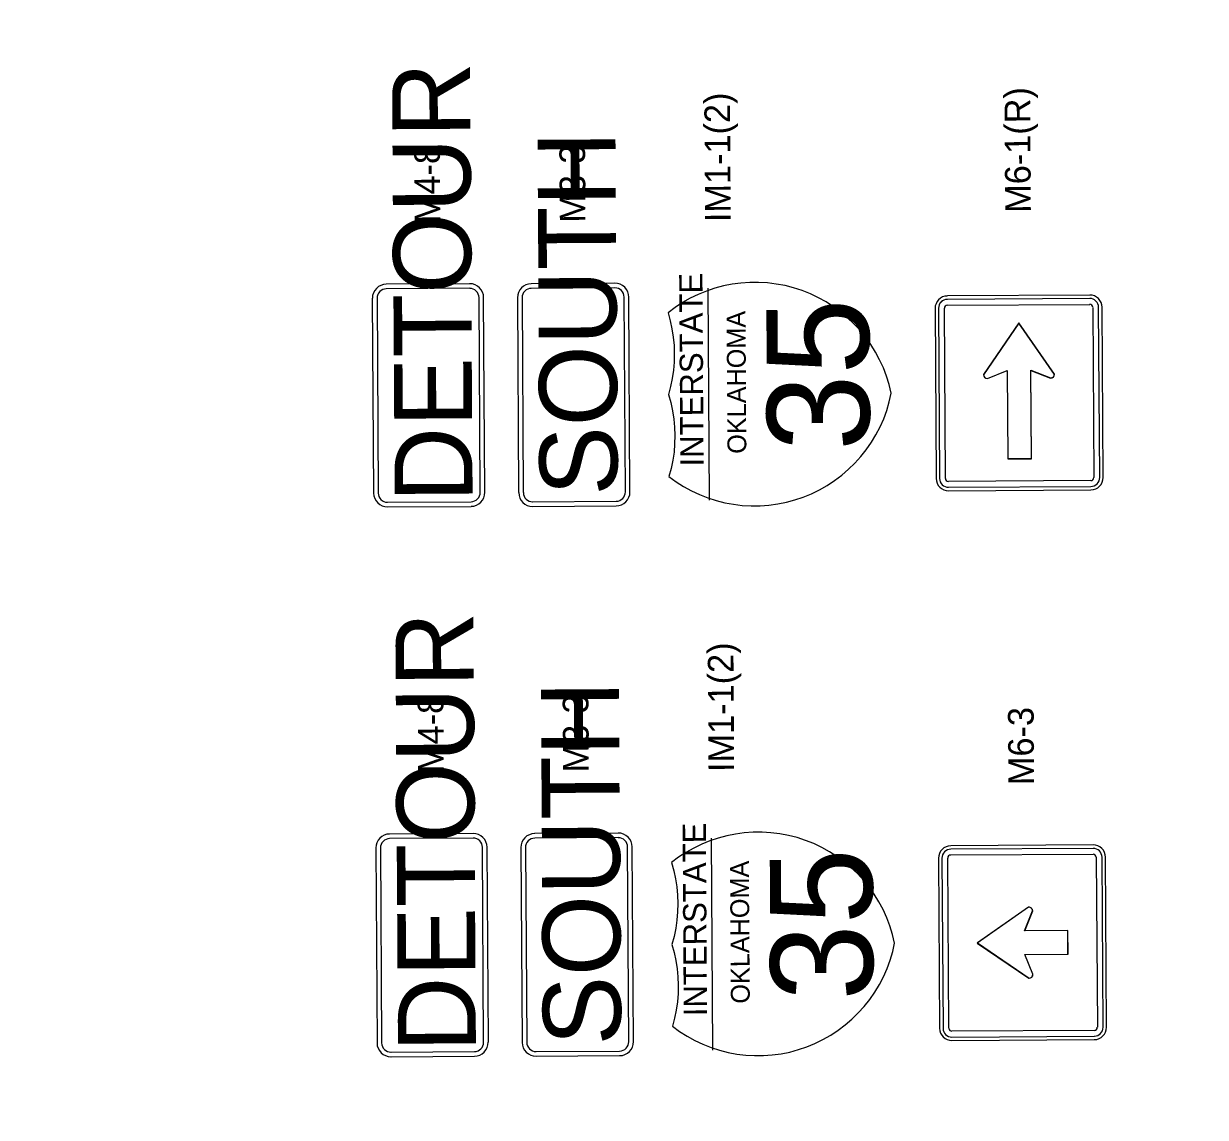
# Model space of a CAD drawing. Extents: x 2135767 to 2151731, y 141839 to 175894.
# Drawn here: x 2139084 to 2140190, y 172875 to 173899 of the extents above; entities that cross this region are included whole.
import ezdxf

# ---------------------------------------------------------------- set-up
doc = ezdxf.new("R2010")
doc.units = 0
doc.layers.add('PR_Phasing_Detour_1', color=7, linetype='Continuous')

msp = doc.modelspace()

# ---------------------------------------------------------------- linework, layer by layer
at = {"layer": 'PR_Phasing_Detour_1'}
for p, q in [((2139501.8, 173655.2), (2139423.7, 173654.7)), ((2139637.6, 173655.7), (2139559.5, 173655.2)), ((2139501.9, 173650.9), (2139423.7, 173650.4)), ((2139511.7, 173459.9), (2139510.6, 173642.2)), ((2139516.1, 173459.9), (2139514.9, 173642.3)), ((2139546.5, 173642.1), (2139547.6, 173459.7)), ((2139550.9, 173642.1), (2139552, 173459.8)), ((2139637.6, 173651.3), (2139559.5, 173650.8)), ((2139647.5, 173460.4), (2139646.4, 173642.7)), ((2139651.8, 173460.4), (2139650.7, 173642.7)), ((2139726.1, 173452.5), (2139724.9, 173650.9)), ((2140082, 173644.6), (2139948.8, 173643.8)), ((2139410.7, 173641.6), (2139411.9, 173459.3)), ((2139415.1, 173641.7), (2139416.2, 173459.3)), ((2139937.3, 173632.2), (2139938.3, 173472.9)), ((2139940.5, 173632.2), (2139941.5, 173472.9)), ((2139940.5, 173632.2), (2139941.5, 173473)), ((2139947, 173473), (2139946, 173632.2)), ((2139947, 173473), (2139946, 173632.2)), ((2140082, 173641.4), (2139948.8, 173640.5)), ((2140082, 173641.4), (2139948.8, 173640.5)), ((2139948.8, 173635.1), (2140082, 173635.9)), ((2139948.8, 173635.1), (2140082, 173635.9)), ((2140084.9, 173633.1), (2140085.9, 173473.8)), ((2140084.9, 173633.1), (2140085.9, 173473.8)), ((2140091.3, 173473.9), (2140090.3, 173633.1)), ((2140091.3, 173473.9), (2140090.3, 173633.1)), ((2140094.6, 173473.9), (2140093.6, 173633.1)), ((2140015.5, 173618.3), (2139982.5, 173570)), ((2140049.1, 173570.4), (2140015.5, 173618.3)), ((2139986.2, 173566.4), (2140004.7, 173573.9)), ((2140004.7, 173573.9), (2140005.2, 173491.3)), ((2140027.4, 173491.4), (2140026.9, 173574)), ((2140026.9, 173574), (2140045.4, 173566.7)), ((2140005.2, 173491.3), (2140027.4, 173491.4)), ((2140083, 173471), (2139949.8, 173470.1)), ((2140083, 173471), (2139949.8, 173470.1)), ((2139949.9, 173464.7), (2140083.1, 173465.5)), ((2139949.9, 173464.7), (2140083.1, 173465.5)), ((2139949.9, 173461.5), (2140083.1, 173462.3)), ((2139425, 173450.7), (2139503.1, 173451.2)), ((2139425, 173446.3), (2139503.1, 173446.8)), ((2139560.7, 173451.1), (2139638.9, 173451.6)), ((2139560.8, 173446.8), (2139638.9, 173447.3)), ((2139505, 173140.7), (2139426.9, 173140.2)), ((2139505.1, 173136.4), (2139426.9, 173135.9)), ((2139640.8, 173141.1), (2139562.7, 173140.7)), ((2139640.8, 173136.8), (2139562.7, 173136.3)), ((2139729.3, 172938), (2139728.1, 173136.3)), ((2139413.9, 173127.1), (2139415.1, 172944.8)), ((2139418.3, 173127.1), (2139419.4, 172944.8)), ((2139514.9, 172945.4), (2139513.8, 173127.7)), ((2139519.3, 172945.4), (2139518.1, 173127.7)), ((2139549.7, 173127.6), (2139550.8, 172945.2)), ((2139554, 173127.6), (2139555.2, 172945.2)), ((2139650.7, 172945.8), (2139649.6, 173128.2)), ((2139655, 172945.9), (2139653.9, 173128.2)), ((2140085.1, 173130.1), (2139951.9, 173129.3)), ((2140085.2, 173126.8), (2139952, 173126)), ((2140085.2, 173126.8), (2139952, 173126)), ((2139940.5, 173117.7), (2139941.5, 172958.4)), ((2139943.7, 173117.7), (2139944.7, 172958.4)), ((2139943.7, 173117.7), (2139944.7, 172958.4)), ((2139950.1, 172958.5), (2139949.2, 173117.7)), ((2139950.1, 172958.5), (2139949.2, 173117.7)), ((2139952, 173120.6), (2140085.2, 173121.4)), ((2139952, 173120.6), (2140085.2, 173121.4)), ((2140088.1, 173118.6), (2140089.1, 172959.3)), ((2140088.1, 173118.6), (2140089.1, 172959.3)), ((2140094.5, 172959.4), (2140093.5, 173118.6)), ((2140094.5, 172959.4), (2140093.5, 173118.6)), ((2140097.7, 172959.4), (2140096.8, 173118.6)), ((2140024.7, 173071.8), (2139976.8, 173038.2)), ((2140021.1, 173049.6), (2140028.4, 173068.2)), ((2140061.4, 173049.9), (2140021.1, 173049.6)), ((2140061.5, 173027.7), (2140061.4, 173049.9)), ((2139976.8, 173038.2), (2140025.1, 173005.2)), ((2140021.3, 173027.4), (2140061.5, 173027.7)), ((2140028.8, 173009), (2140021.3, 173027.4)), ((2140086.2, 172956.4), (2139953, 172955.6)), ((2140086.2, 172956.4), (2139953, 172955.6)), ((2139953.1, 172950.2), (2140086.3, 172951)), ((2139953.1, 172950.2), (2140086.3, 172951)), ((2139953.1, 172946.9), (2140086.3, 172947.8)), ((2139428.2, 172936.2), (2139506.3, 172936.7)), ((2139563.9, 172936.6), (2139642.1, 172937.1)), ((2139428.2, 172931.8), (2139506.3, 172932.3)), ((2139563.9, 172932.3), (2139642.1, 172932.8))]:
    msp.add_line(p, q, dxfattribs=at)
for points in [[(2139688.3, 173474.8), (2139695, 173469.9), (2139702, 173465.5), (2139709.3, 173461.5), (2139716.8, 173458), (2139724.5, 173454.9), (2139732.5, 173452.4), (2139740.5, 173450.3), (2139748.7, 173448.8), (2139756.9, 173447.8), (2139765.2, 173447.4), (2139773.5, 173447.4), (2139781.8, 173448), (2139790, 173449.1), (2139798.2, 173450.8), (2139806.2, 173452.9), (2139814, 173455.6), (2139821.7, 173458.7), (2139829.2, 173462.4), (2139836.4, 173466.5), (2139843.3, 173471.1), (2139850, 173476.1), (2139856.3, 173481.5), (2139862.2, 173487.3), (2139867.8, 173493.4), (2139872.9, 173499.9), (2139877.7, 173506.8), (2139882, 173513.9), (2139885.8, 173521.2), (2139889.2, 173528.8), (2139892, 173536.6), (2139894.4, 173544.6), (2139896.2, 173552.7), (2139894.3, 173560.8), (2139891.8, 173568.7), (2139888.9, 173576.5), (2139885.4, 173584), (2139881.5, 173591.3), (2139877.1, 173598.4), (2139872.3, 173605.1), (2139867.1, 173611.6), (2139861.4, 173617.7), (2139855.4, 173623.4), (2139849, 173628.7), (2139842.3, 173633.6), (2139835.3, 173638.1), (2139828.1, 173642.1), (2139820.6, 173645.7), (2139812.8, 173648.8), (2139804.9, 173651.3), (2139796.9, 173653.4), (2139788.7, 173654.9), (2139780.5, 173655.9), (2139772.2, 173656.4), (2139763.9, 173656.4), (2139755.6, 173655.8), (2139747.4, 173654.7), (2139739.2, 173653.1), (2139731.2, 173651), (2139723.3, 173648.3), (2139715.7, 173645.2), (2139708.2, 173641.6), (2139701, 173637.5), (2139694, 173632.9), (2139687.4, 173627.9), (2139689.5, 173620.5), (2139691.1, 173612.9), (2139692.3, 173605.2), (2139693.1, 173597.5), (2139693.3, 173589.7), (2139693.2, 173581.9), (2139692.5, 173574.2), (2139691.4, 173566.5), (2139689.8, 173558.9), (2139687.8, 173551.4), (2139689.9, 173543.9), (2139691.6, 173536.3), (2139692.8, 173528.6), (2139693.5, 173520.9), (2139693.8, 173513.2), (2139693.6, 173505.4), (2139693, 173497.6), (2139691.9, 173490), (2139690.3, 173482.3), (2139688.3, 173474.8)], [(2140015.5, 173618.6), (2139982.5, 173570.3)], [(2140049.1, 173570.7), (2140015.5, 173618.6)], [(2139986.2, 173566.6), (2140004.7, 173574.1), (2140005.2, 173491.6), (2140027.4, 173491.7), (2140026.9, 173574.3), (2140045.4, 173567)], [(2139691.5, 172960.3), (2139698.2, 172955.4), (2139705.2, 172951), (2139712.5, 172947), (2139720, 172943.4), (2139727.7, 172940.4), (2139735.6, 172937.8), (2139743.7, 172935.8), (2139751.9, 172934.3), (2139760.1, 172933.3), (2139768.4, 172932.8), (2139776.7, 172932.9), (2139785, 172933.5), (2139793.2, 172934.6), (2139801.4, 172936.2), (2139809.4, 172938.4), (2139817.2, 172941.1), (2139824.9, 172944.2), (2139832.4, 172947.9), (2139839.6, 172952), (2139846.5, 172956.5), (2139853.2, 172961.5), (2139859.5, 172966.9), (2139865.4, 172972.7), (2139871, 172978.9), (2139876.1, 172985.4), (2139880.9, 172992.2), (2139885.2, 172999.3), (2139889, 173006.7), (2139892.3, 173014.3), (2139895.2, 173022.1), (2139897.6, 173030.1), (2139899.4, 173038.2), (2139897.5, 173046.2), (2139895, 173054.2), (2139892.1, 173061.9), (2139888.6, 173069.5), (2139884.7, 173076.8), (2139880.3, 173083.9), (2139875.5, 173090.6), (2139870.2, 173097.1), (2139864.6, 173103.2), (2139858.6, 173108.9), (2139852.2, 173114.2), (2139845.5, 173119.1), (2139838.5, 173123.6), (2139831.3, 173127.6), (2139823.8, 173131.2), (2139816, 173134.2), (2139808.1, 173136.8), (2139800.1, 173138.8), (2139791.9, 173140.4), (2139783.7, 173141.4), (2139775.4, 173141.9), (2139767.1, 173141.8), (2139758.8, 173141.3), (2139750.6, 173140.2), (2139742.4, 173138.6), (2139734.4, 173136.4), (2139726.5, 173133.8), (2139718.9, 173130.7), (2139711.4, 173127), (2139704.2, 173122.9), (2139697.2, 173118.4), (2139690.6, 173113.4), (2139692.7, 173105.9), (2139694.3, 173098.4), (2139695.5, 173090.7), (2139696.3, 173082.9), (2139696.5, 173075.2), (2139696.4, 173067.4), (2139695.7, 173059.7), (2139694.6, 173052), (2139693, 173044.4), (2139691, 173036.9), (2139693.1, 173029.4), (2139694.8, 173021.8), (2139696, 173014.1), (2139696.7, 173006.4), (2139697, 172998.6), (2139696.8, 172990.9), (2139696.2, 172983.1), (2139695.1, 172975.4), (2139693.5, 172967.8), (2139691.5, 172960.3)], [(2140024.8, 173071.8), (2139976.9, 173038.3)], [(2140028.9, 173009), (2140021.4, 173027.4), (2140061.7, 173027.7), (2140061.5, 173049.9), (2140021.3, 173049.6), (2140028.6, 173068.2)], [(2139976.9, 173038.3), (2140025.2, 173005.2)]]:
    msp.add_lwpolyline(points, dxfattribs=at)
msp.add_circle((2140069.5, 171591.4), 4302.2, dxfattribs=at)
for centre, radius, start, end in [((2139423.8, 173641.7), 13, 90.3555, 180.3555), ((2139501.9, 173642.2), 13, 0.3555, 90.3555), ((2139559.5, 173642.2), 13, 90.3555, 180.3555), ((2139637.7, 173642.6), 13, 0.3555, 90.3555), ((2139423.8, 173641.7), 8.68, 90.3555, 180.3555), ((2139501.9, 173642.2), 8.68, 0.3555, 90.3555), ((2139559.5, 173642.2), 8.68, 90.3555, 180.3555), ((2139637.7, 173642.6), 8.68, 0.3555, 90.3555), ((2139948.8, 173632.2), 11.5, 90.3555, 180.3555), ((2140082, 173633.1), 11.5, 0.3555, 90.3555), ((2139948.8, 173632.2), 8.29, 90.3555, 180.3555), ((2139948.8, 173632.3), 8.29, 90.3555, 180.3555), ((2139948.8, 173632.2), 2.86, 90.3555, 180.3555), ((2139948.8, 173632.3), 2.86, 90.3555, 180.3555), ((2140082, 173633.1), 8.29, 0.3555, 90.3555), ((2140082, 173633.1), 8.29, 0.3555, 90.3555), ((2140082, 173633.1), 2.86, 0.3555, 90.3555), ((2140082, 173633.1), 2.86, 0.3555, 90.3555), ((2139986.2, 173570.3), 3.7, 180.3555, 270.3555), ((2139986.2, 173570.1), 3.7, 180.3555, 270.3555), ((2140045.4, 173570.7), 3.7, 270.3555, 0.3555), ((2140045.4, 173570.4), 3.7, 270.3555, 0.3555), ((2139949.8, 173473), 11.5, 180.3555, 270.3555), ((2139949.8, 173473), 8.29, 180.3555, 270.3555), ((2139949.8, 173473), 8.29, 180.3555, 270.3555), ((2139949.8, 173473), 2.86, 180.3555, 270.3555), ((2139949.8, 173473), 2.86, 180.3555, 270.3555), ((2140083, 173473.8), 2.86, 270.3555, 0.3555), ((2140083, 173473.8), 2.86, 270.3555, 0.3555), ((2140083, 173473.8), 11.5, 270.3555, 0.3555), ((2140083, 173473.8), 8.29, 270.3555, 0.3555), ((2140083, 173473.8), 8.29, 270.3555, 0.3555), ((2139424.9, 173459.4), 13, 180.3555, 270.3555), ((2139424.9, 173459.4), 8.68, 180.3555, 270.3555), ((2139503, 173459.9), 13, 270.3555, 0.3555), ((2139503, 173459.9), 8.68, 270.3555, 0.3555), ((2139560.7, 173459.8), 13, 180.3555, 270.3555), ((2139560.7, 173459.8), 8.68, 180.3555, 270.3555), ((2139638.8, 173460.3), 8.68, 270.3555, 0.3555), ((2139638.8, 173460.3), 13, 270.3555, 0.3555), ((2139427, 173127.2), 13, 90.3555, 180.3555), ((2139427, 173127.2), 8.68, 90.3555, 180.3555), ((2139505.1, 173127.7), 13, 0.3555, 90.3555), ((2139505.1, 173127.7), 8.68, 0.3555, 90.3555), ((2139562.7, 173127.6), 13, 90.3555, 180.3555), ((2139562.7, 173127.6), 8.68, 90.3555, 180.3555), ((2139640.9, 173128.1), 13, 0.3555, 90.3555), ((2139640.9, 173128.1), 8.68, 0.3555, 90.3555), ((2139952, 173117.7), 11.5, 90.3555, 180.3555), ((2139952, 173117.7), 8.29, 90.3555, 180.3555), ((2139952, 173117.7), 8.29, 90.3555, 180.3555), ((2140085.2, 173118.5), 11.5, 0.3555, 90.3555), ((2140085.2, 173118.5), 8.29, 0.3555, 90.3555), ((2140085.2, 173118.5), 8.29, 0.3555, 90.3555), ((2139952, 173117.7), 2.86, 90.3555, 180.3555), ((2139952, 173117.7), 2.86, 90.3555, 180.3555), ((2140085.2, 173118.5), 2.86, 0.3555, 90.3555), ((2140085.2, 173118.5), 2.86, 0.3555, 90.3555), ((2140024.7, 173068.1), 3.7, 0.3555, 90.3555), ((2140024.9, 173068.1), 3.7, 0.3555, 90.3555), ((2140025.1, 173008.9), 3.7, 270.3555, 0.3555), ((2140025.2, 173008.9), 3.7, 270.3555, 0.3555), ((2139953, 172958.5), 11.5, 180.3555, 270.3555), ((2139953, 172958.5), 8.29, 180.3555, 270.3555), ((2139953, 172958.5), 8.29, 180.3555, 270.3555), ((2139953, 172958.5), 2.86, 180.3555, 270.3555), ((2139953, 172958.5), 2.86, 180.3555, 270.3555), ((2140086.2, 172959.3), 2.86, 270.3555, 0.3555), ((2140086.2, 172959.3), 2.86, 270.3555, 0.3555), ((2140086.2, 172959.3), 11.5, 270.3555, 0.3555), ((2140086.2, 172959.3), 8.29, 270.3555, 0.3555), ((2140086.2, 172959.3), 8.29, 270.3555, 0.3555), ((2139506.2, 172945.3), 13, 270.3555, 0.3555), ((2139506.2, 172945.3), 8.68, 270.3555, 0.3555), ((2139642, 172945.8), 13, 270.3555, 0.3555), ((2139642, 172945.8), 8.68, 270.3555, 0.3555), ((2139428.1, 172944.8), 13, 180.3555, 270.3555), ((2139428.1, 172944.8), 8.68, 180.3555, 270.3555), ((2139563.9, 172945.3), 13, 180.3555, 270.3555), ((2139563.9, 172945.3), 8.68, 180.3555, 270.3555)]:
    msp.add_arc(centre, radius, start, end, dxfattribs=at)

# ---------------------------------------------------------------- texts
for s, height, p in [('DETOUR', 72.94, (2139504.6, 173450.9)), ('IM1-1(2)', 24, (2139746.1, 173712.9)), ('M6-1(R)', 24, (2140026.9, 173721.6)), ('SOUTH', 72.94, (2139640.3, 173456.9)), ('M4-8', 24, (2139474.4, 173712)), ('M3-3', 24, (2139610.2, 173712.4)), ('INTERSTATE', 21.78, (2139720.7, 173484.2)), ('35', 95.86, (2139876.1, 173499)), ('OKLAHOMA', 17.65, (2139760.7, 173496.1)), ('DETOUR', 72.94, (2139507.7, 172936.4)), ('IM1-1(2)', 24, (2139749.3, 173198.3)), ('M4-8', 24, (2139477.6, 173197.4)), ('SOUTH', 72.94, (2139643.5, 172942.4)), ('M3-3', 24, (2139613.3, 173197.9)), ('M6-3', 24, (2140029.9, 173186)), ('INTERSTATE', 21.78, (2139723.9, 172969.7)), ('OKLAHOMA', 17.65, (2139763.9, 172981.5)), ('35', 95.86, (2139879.3, 172984.5))]:
    msp.add_text(s, height=height, rotation=90.3555, dxfattribs=at).set_placement(p)

doc.saveas('drawing.dxf')
